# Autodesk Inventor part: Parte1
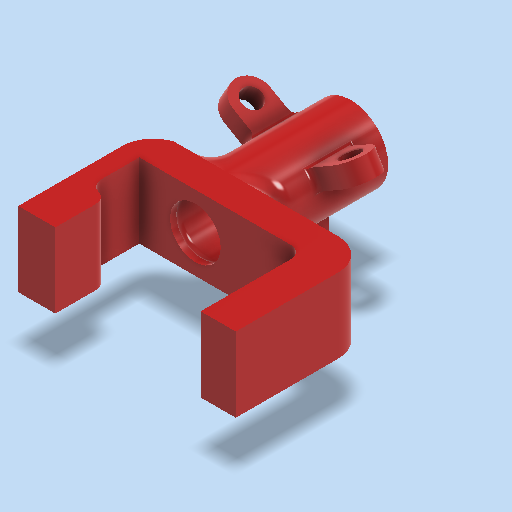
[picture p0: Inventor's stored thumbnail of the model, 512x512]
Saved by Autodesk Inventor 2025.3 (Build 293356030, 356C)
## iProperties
Created: 2026-05
Part Number: Parte1
Material: Generico
Document SubType Name: Modeling
Designer: Ryzen5700u
Density: 1 g/cm^3
Appearance: Rosso
Author: Ryzen5700u
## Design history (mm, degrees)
sketch "Schizzo1"
  geometry: C1 r 6 at (0, 0); C2 r 4.6 at (0, 0); 1 further point
  constraints: 2 centre point, 1 coincident
  dimensions: "d0" = 12 diameter of C1; "d1" = 1.4 radial gap between concentric circles of C1 C2
extrude "Estrusione1" new body sketch "Schizzo1" distance "d2" = 25; taper "d3" = 0 deg
node "Piano di lavoro1"
sketch "Schizzo2"
  geometry: L1 (-6, 0)-(-6, 25) reference; L2 (-6, 11)-(-13, 11); L3 (-13, 11)-(-13, 5); L4 (-13, 5)-(-6, 5); L5 (-6, 5)-(-6, 11); L6 (-4.6, 25)-(4.6, 25) reference; L7 (-13, 8)-(-6, 8); L8 (-6, 11)-(-5, 11); L9 (-5, 11)-(-5, 5); L10 (-5, 5)-(-6, 5); L11 (-6, 5)-(-6, 11); L12 (6, 25)-(-6, 25) reference; L13 (-6, 25)-(-9, 25); L14 (-9, 25)-(-9, 11); L15 (6, 25)-(-6, 25) reference; L16 (6, 0)-(-6, 0) reference; L17 (-6, 25)-(-5, 25); L18 (-5, 25)-(-5, 11); L19 (-5, 11)-(-6, 11); L20 (-6, 11)-(-6, 25); C1 r 1.6 at (-10, 8); A1 r 9.667 centre (-15.667, 18) between (-9, 11) and (-9, 25); 6 further points
  constraints: 30 end point, 6 parallel, 4 horizontal, 4 perpendicular, 3 point on line, 2 centre point, 2 midpoint, 2 point on circle, 1 tangent
  dimensions: "d5" = 7 distance of L4.end L3.end; "d6" = 6 distance of L3.end L2.end; "d7" = 14 distance between parallel lines of L6 L2; "d11" = 3.2 diameter of C1; "d15" = 1 distance of L4.end L9.end; "d19" = 3 distance from line of L3 C1.centre; "d20" = 3 distance of L1.end L13.end
extrude "Estrusione2" join sketch "Schizzo2" stored distance "d9" = 3; taper "d10" = 0 deg
pattern_circular "Serie circolare1" dims angle "d13" = 360 deg
fillet "Raccordo1" dims "d16" = 3
fillet "Raccordo2" dims "d17" = 1
fillet "Raccordo3" dims "d18" = 0.5
fillet "Raccordo4" dims "d21" = 1
fillet "Raccordo5" dims "d22" = 1
sketch "Schizzo3"
  geometry: L1 (-0.311, 7)-(-0.311, -14) reference; L2 (3.382, -14)-(3.382, 7) reference; L3 (-0.311, 0)-(3.382, 0); L4 (3.382, 0)-(3.382, -1); L5 (3.382, -1)-(-0.311, -1); L6 (-0.311, -1)-(-0.311, 0); L7 (0, 0)-(3.071, 0) reference; L8 (3.071, -6)-(0, -6) reference; L9 (3.071, 0)-(3.071, -6) reference; L10 (0, -6)-(0, 0) reference; 5 further points
  constraints: 8 end point, 2 parallel, 2 point on line, 1 horizontal, 1 perpendicular
  dimensions: "d24" = 1 distance of L3.end L4.end
extrude "Estrusione3" cut sketch "Schizzo3" distance "d25" = 1; taper "d26" = 0 deg; dims "d33" = 0.5, "d34" = 0
pattern_linear "Serie rettangolare1" dims "d29" = 2, "d37" = 2
pattern_circular "Serie circolare2" dims "d31" = 360 deg
fillet "Raccordo6" dims "d38" = 0.5
fillet "Raccordo7" dims "d39" = 0.5
pattern_circular "Serie circolare3" dims angle "d41" = 360 deg
sketch "Schizzo4"
  geometry: C1 r 6 at (0, 0) reference; C2 r 4.6 at (0, 0) reference; C3 r 4.075 at (0, 0); 1 further point
  constraints: 1 centre point, 1 coincident
  dimensions: "d43" = 8.15 diameter of C3
extrude "Estrusione4" join sketch "Schizzo4" distance "d44" = 1; taper "d45" = 0 deg
fillet "Raccordo8" dims "d46" = 2
sketch "Schizzo5"
  geometry: L1 (-23, -6)-(23, -6); L2 (23, -6)-(23, 6); L3 (23, 6)-(-23, 6); L4 (-23, 6)-(-23, -6); L5 (-23, -6)-(23, 6); L6 (23, -6)-(-23, 6); L7 (-46, 6)-(-46, -6); L8 (-11.981, 6)-(-11.981, -6); C1 r 1 at (-8.25, 0); C2 r 1 at (19.55, 0); C3 r 4.6 at (0, 0) reference; C4 r 6 at (0, 0); A1 r 6 centre (0, 0) between (5.416, 2.584) and (-5.85, 1.335) reference; A2 r 1 centre (-8.25, 0) between (-9.05, -0.6) and (-9.05, 0.6) reference; A3 r 1 centre (19.55, 0) between (20.35, 0.6) and (20.35, -0.6) reference; 7 further points
  constraints: 16 end point, 4 point on line, 3 centre point, 3 coincident, 3 perpendicular, 2 midpoint, 2 parallel, 1 horizontal
  dimensions: "d47" = 46 distance of L3.end L2.end; "d48" = 12 distance of L2.end L1.end; "d49" = 46 distance from line of point (0, 0) L7; "d50" = 2 diameter of C1; "d51" = 2 diameter of C2
extrude "Estrusione5" join sketch "Schizzo5" distance "d52" = 5; taper "d53" = 0 deg
sketch "Schizzo6"
  geometry: L1 (23, 6)-(-11.981, 6) reference; L2 (-11.981, -6)-(23, -6) reference; L3 (23, -6)-(23, 6) reference; L4 (23, 6)-(-23, 6) reference; L5 (-6.017, 6)-(-6.017, -6); L6 (0, 6)-(23, 6) reference; L7 (17.344, 6)-(17.344, -6); L8 (-11.981, 6)-(-11.981, -6) reference; L9 (23, 6)-(-11.981, 6) reference; L10 (-11.981, 6)-(-11.981, -6) reference; L11 (-11.981, -6)-(23, -6) reference; L12 (23, -6)-(23, 6) reference; C1 r 4.075 at (0, 0) reference; C2 r 4.075 at (0, 0) reference; 5 further points
  constraints: 5 point on line, 4 end point, 2 perpendicular
  node "Linea chiusa proiettata4"
  node "Linea chiusa proiettata5"
node "Piano di lavoro2"
extrude "Estrusione6" join sketch "Schizzo6" distance "d54" = 16.5; taper "d55" = 0 deg
sketch "Schizzo7"
  geometry: L1 (17.344, 5)-(-6.017, 5) reference; L2 (-6.017, 5)-(-9.017, 5); L3 (-9.017, 5)-(-9.017, 13); L4 (-9.017, 13)-(-6.017, 13); L5 (-6.017, 13)-(-6.017, 5); 4 further points
  constraints: 8 end point, 2 parallel, 1 horizontal, 1 perpendicular
  dimensions: "d56" = 3 distance of L3.end L4.end; "d57" = 8 distance of L2.end L3.end
extrude "Estrusione7" cut sketch "Schizzo7" extent not by distance; stored distance "d58" = 0; taper "d59" = 0 deg
fillet "Raccordo9" dims "d60" = 5
fillet "Raccordo10" dims "d61" = 2
node "Solido1"
node "Linea chiusa proiettata1"
node "Linea chiusa proiettata2"
node "Linea chiusa proiettata3"
node "Riferimento1"
node "Riferimento2"
node "Riferimento3"
other parameters: "d4" = -25
